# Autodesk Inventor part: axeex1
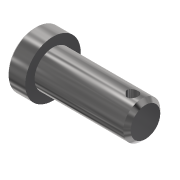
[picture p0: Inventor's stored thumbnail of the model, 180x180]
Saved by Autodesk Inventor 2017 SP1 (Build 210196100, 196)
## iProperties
Created: 2006-05
Part Number: axeex1
Material: Acier inoxydable
Document SubType Name: Modeling
Designer: Administrateur
Manufacturer: Standard
Standards Organization: Custom
Mass: 22.0525 g
Surface Area: 14.1824 cm^2
Volume: 2.75657 cm^3
Density: 8 g/cm^3
Appearance: Semi-poli
Author: Administrateur
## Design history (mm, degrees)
sketch "Esquisse1"
  geometry: L1 (-30, 0)-(-30, 7.5); L2 (-30, 7.5)-(-25, 7.5); L3 (-25, 7.5)-(-25, 5); L4 (-25, 5)-(0, 5); L5 (0, 5)-(0, 0); L6 (0, 0)-(-30, 0); 1 further point
  constraints: 12 end point, 4 parallel, 1 coincident, 1 perpendicular, 1 vertical
  dimensions: "d0" = 15 diameter of L2 L6; "d1" = 10 diameter of L4 L6; "d2" = 25 distance of L3.end L4.end; "d3" = 5 distance of L1.end L2.end
revolve "Révolution1" sketch "Esquisse1" stored, may be unused: angle "d4" = 90 deg
chamfer "Chanfrein1" distance "d5" = 1; stored, may be unused: second distance "d6" = 2, angle "d7" = 45 deg
chamfer "Chanfrein2" distance "d8" = 0.5; stored, may be unused: second distance "d9" = 2, angle "d10" = 45 deg
sketch "Esquisse2"
  geometry: L1 (5, 6.474)-(3.5, 6.474); L2 (3.5, 6.474)-(3.5, -7.851); L3 (3.5, -7.851)-(5, -7.851); L4 (5, -7.851)-(5, 6.474); L5 (25, 7.5)-(25, -7.5) reference
  constraints: 8 end point, 2 parallel, 1 horizontal, 1 perpendicular
  dimensions: "d11" = 1.5 distance of L1.start L1.end; "d12" = 20 distance between parallel lines of L4 L5
revolve "Révolution2" sketch "Esquisse2" stored, may be unused: angle "d13" = 90 deg
node "Solide1"
node "Corps solides"
node "Corps surfaciques"
